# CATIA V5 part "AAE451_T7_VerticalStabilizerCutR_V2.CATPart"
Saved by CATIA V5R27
Part number: VSRH
Bounding box of the stored display mesh (mm): x -0.013 to 222.987, y 89.281 to 111.19, z 0 to 225
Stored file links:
  W:\AAE 451\AAE451_T7_TailAssembly_V2\AAE451_T7_VerticalStabilizerCutR_V2.CATPart
  CATDrawing1.CATDrawing
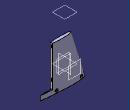
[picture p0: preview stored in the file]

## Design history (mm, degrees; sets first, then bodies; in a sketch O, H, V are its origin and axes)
Set1 "GeometryFromExcel"
  Point1: (1, 0.001, 0)
  Point2: (0.95, 0.0067, 0)
  Point3: (0.9, 0.0121, 0)
  Point4: (0.8, 0.0219, 0)
  Point5: (0.7, 0.0305, 0)
  Point6: (0.6, 0.038, 0)
  Point7: (0.5, 0.0441, 0)
  Point8: (0.4, 0.0484, 0)
  Point9: (0.3, 0.05, 0)
  Point10: (0.25, 0.0495, 0)
  Point11: (0.2, 0.0478, 0)
  Point12: (0.15, 0.0445, 0)
  Point13: (0.1, 0.039, 0)
  Point14: (0.075, 0.035, 0)
  Point15: (0.05, 0.0296, 0)
  Point16: (0.025, 0.0218, 0)
  Point17: (0.0125, 0.0158, 0)
  Point18: (0, 0, 0)
  Point19: (0.0125, -0.0158, 0)
  Point20: (0.025, -0.0218, 0)
  Point21: (0.05, -0.0296, 0)
  Point22: (0.075, -0.035, 0)
  Point23: (0.1, -0.039, 0)
  Point24: (0.15, -0.0445, 0)
  Point25: (0.2, -0.0478, 0)
  Point26: (0.25, -0.0495, 0)
  Point27: (0.3, -0.05, 0)
  Point28: (0.4, -0.0484, 0)
  Point29: (0.5, -0.0441, 0)
  Point30: (0.6, -0.038, 0)
  Point31: (0.7, -0.0305, 0)
  Point32: (0.8, -0.0219, 0)
  Point33: (0.9, -0.0121, 0)
  Point34: (0.95, -0.0067, 0)
  Point35: (1, -0.001, 0)
  Point36: (1, 0.001, 0)
  Point37: (0.95, 0.0067, 0)
  Point38: (0.9, 0.0121, 0)
  Point39: (0.8, 0.0219, 0)
  Point40: (0.7, 0.0305, 0)
  Point41: (0.6, 0.038, 0)
  Point42: (0.5, 0.0441, 0)
  Point43: (0.4, 0.0484, 0)
  Point44: (0.3, 0.05, 0)
  Point45: (0.25, 0.0495, 0)
  Point46: (0.2, 0.0478, 0)
  Point47: (0.15, 0.0445, 0)
  Point48: (0.1, 0.039, 0)
  Point49: (0.075, 0.035, 0)
  Point50: (0.05, 0.0296, 0)
  Point51: (0.025, 0.0218, 0)
  Point52: (0.0125, 0.0158, 0)
  Point53: (0, 0, 0)
  Point54: (0.0125, -0.0158, 0)
  Point55: (0.025, -0.0218, 0)
  Point56: (0.05, -0.0296, 0)
  Point57: (0.075, -0.035, 0)
  Point58: (0.1, -0.039, 0)
  Point59: (0.15, -0.0445, 0)
  Point60: (0.2, -0.0478, 0)
  Point61: (0.25, -0.0495, 0)
  Point62: (0.3, -0.05, 0)
  Point63: (0.4, -0.0484, 0)
  Point64: (0.5, -0.0441, 0)
  Point65: (0.6, -0.038, 0)
  Point66: (0.7, -0.0305, 0)
  Point67: (0.8, -0.0219, 0)
  Point68: (0.9, -0.0121, 0)
  Point69: (0.95, -0.0067, 0)
  Point70: (1, -0.001, 0)
  Curve1: Elements (Point36; Point37; Point38; Point39; Point40; Point41; Point42; Point43; Point44; Point45; Point46; Point47; Point48; Point49; Point50; Point51; Point52; Point53; Point54; Point55; Point56; Point57; Point58; Point59; Point60; Point61; Point62; Point63; Point64; Point65; Point66; Point67; Point68; Point69; Point70)
  Sketch1 on xy-plane, origin (0, 0, 0), H (1, 0, 0), V (0, 1, 0)
    projected curve E1 from edge of Curve1
    line L1 (1, 0.001) -> (1.0001, -0.001)
    point P3 (1, 0.001)
    point P4 (1.0001, -0.001)
    reference projected point E2 (1, 0.001) from Point1
    reference projected point E3 (1, -0.001) from Point35
    frozenspline C1
    line L2 (222.9868, -0.27) -> (222.9868, 0.1983)
    coincidence: P3 E2, P4 E3
    fix: C1
Body1 (main body)
  Plane1: type Offset, RefPlane xy-plane, Offset 225
  Sketch2 on xy-plane, origin (0, 0, 0), H (1, 0, 0), V (0, 1, 0)
    projected curve E1 from Sketch1.C1
    point P1 (222.9868, 0.1983)
    line L1 (222.9868, 0.1983) -> (222.9868, -0.27)
    point P3 (222.9868, 0.1983)
    coincidence: P3 P1
  Sketch3 on Plane1, origin (0, 0, 225), H (1, 0, 0), V (0, 1, 0)
    frozenspline C1
    line L1 (222.9868, 0.1983) -> (222.9868, -0.1225)
    fix: C1
  Loft1: solid, Sections (Sketch2; Sketch3)
  Plane2: type Offset, RefPlane zx-plane, Offset 50
  Sketch4 on Plane2, origin (0, 50, 0), H (0, 0, 1), V (1, 0, 0)
    line L1 (0, 227.8345) -> (23.3, 227.8345)
    line L2 (23.3, 227.8345) -> (23.3, -7.6138)
    line L3 (23.3, -7.6138) -> (0, -7.6138)
    line L4 (0, -7.6138) -> (0, 227.8345)
    reference projected line E1 (0, 222.9868) -> (0, -0.0132) from edge [face of Loft1 | face of Loft1]
    distance L4 L2 = 23.3
    distance L1 L3 = 235.4483
    vertical: L4 V, L2 V
    horizontal: L1 H, L3 H
    coincidence: L4 E1
  Pocket1: profile Sketch4, direction (0, -1, 0), up to zx-plane
  Sketch5 on zx-plane, origin (0, 0, 0), H (-1, 0, 0), V (0, 0, 1)
    line L1 (-222.9868, 225) -> (-167.2368, 225)
    line L2 (-167.2368, 225) -> (-167.2368, 23.3)
    line L3 (-167.2368, 23.3) -> (-222.9868, 23.3)
    line L4 (-222.9868, 23.3) -> (-222.9868, 225)
    reference projected line E1 (-7.2628, 23.3) -> (-222.9868, 23.3) from edge [face of Loft1 | face of Pocket1 from Sketch4.L2]
    reference projected line E2 (-222.9868, 23.3) -> (-222.9868, 225) from edge [face of Loft1 | face of Loft1]
    reference projected line E3 (-222.9868, 225) -> (-70.2471, 225) from edge [face of Loft1 | face of Loft1]
    distance L4 L2 = 55.75
    distance E3 L1 = 0
    horizontal: L1 H, L3 H
    vertical: L2 V, L4 V
    coincidence: L3 E1, L4 E2
  Pocket2: profile Sketch5, direction (0, -1, 0), through (limit type 3), opposite side through (limit type 3)
  Plane3: type Offset, RefPlane zx-plane, Offset 9, reversed
  Sketch6 on Plane3, origin (9.6807, -9, -4.8499), H (1, 0, 0), V (0, 0, -1)
    point P1 (13.3061, -16.4999)
    reference projected line E1 (213.3061, -4.8499) -> (-9.6939, -4.8499) from edge [face of Loft1 | face of Loft1]
    reference projected line E2 (157.5561, -28.1499) -> (213.3061, -28.1499) from edge [face of Loft1 | face of Pocket2 from Sketch5.L3]
    reference projected line E3 (213.3061, -4.8499) -> (213.3061, -28.1499) from edge [face of Loft1 | face of Loft1]
    distance P1 E3 = 200
    equidistance: E1 E2 P1
  Hole1: placed by Sketch6, at (22.9868, -9, 11.65) direction (0, 1, 0), diameter 5, through (limit type 6), counterbore diameter 15, counterbore depth 5
  RectPattern1: of Hole1, direction 1 instances 2, spacing 125, along xy-plane
  Sketch7 on face of Pocket2 from Sketch5.L2, origin (167.2368, 0, 0), H (0, 1, 0), V (0, 0, 1)
    construction line L1 (-5.5, 225) -> (5.5, 225)
    construction line L2 (5.5, 225) -> (5.5, 48.3)
    construction line L3 (5.5, 48.3) -> (-5.5, 48.3)
    construction line L4 (-5.5, 48.3) -> (-5.5, 225)
    reference intersected line E1 through (0, 225) direction (-1, 0) from Plane1
    line L5 (-0.5, 218) -> (0.5, 218)
    line L6 (0.5, 218) -> (0.5, 202)
    line L7 (0.5, 202) -> (-0.5, 202)
    line L8 (-0.5, 202) -> (-0.5, 218)
    line L9 (-0.5, 71.3) -> (0.5, 71.3)
    line L10 (0.5, 71.3) -> (0.5, 55.3)
    line L11 (0.5, 55.3) -> (-0.5, 55.3)
    line L12 (-0.5, 55.3) -> (-0.5, 71.3)
    point P11 (0.5, 55.3)
    distance L3 L1 = 176.7
    length L1 = 11
    length L11 = 1
    length L10 = 16
    distance L3 P11 = 7
    distance L5 L1 = 7
    length L6 = 16
    length L7 = 1
    horizontal: L1 H, L3 H, L5 H, L7 H, L9 H, L11 H
    vertical: L2 V, L4 V, L6 V, L8 V, L10 V, L12 V
    coincidence: L1 E1
    symmetry: L4 L2 V, L12 L10 V, L8 L6 V
  Pocket3: profile Sketch7, direction (-1, 0, 0), length 13.7
  Mirror1: of the body so far, about Plane2
  Split1: SplitPlane Plane2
